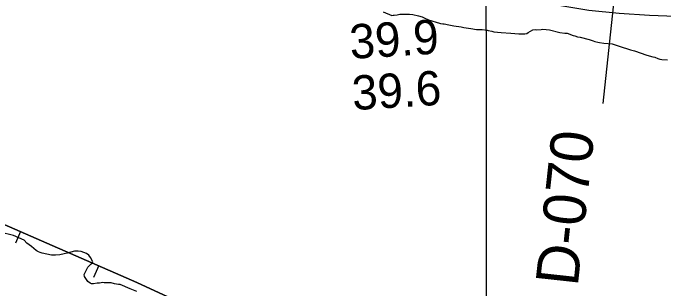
# Model space of a CAD drawing. Extents: x 3279314 to 3317160, y 734079 to 759431.
# Drawn here: x 3290400 to 3291669, y 751596 to 752135 of the extents above; entities that cross this region are included whole.
import ezdxf

# ---------------------------------------------------------------- set-up
doc = ezdxf.new("R2010")
doc.units = 0
for name, color, linetype in [('V-BORW-LINE', 7, 'Continuous'), ('V-GRID-MAJR', 7, 'Continuous'), ('V-RIVR-RANG', 7, 'Continuous'), ('V-RIVR-RANG-IDEN', 7, 'Continuous'), ('V-SITE-VEGE', 7, 'Continuous'), ('V-TOPO-MINR', 7, 'Continuous')]:
    doc.layers.add(name, color=color, linetype=linetype)

msp = doc.modelspace()

# ---------------------------------------------------------------- linework, layer by layer
at = {"layer": 'V-BORW-LINE'}
for p, q in [((3290414.3, 751708.5), (3290404.3, 751685.6)), ((3290567.1, 751642), (3290557.1, 751619))]:
    msp.add_line(p, q, dxfattribs=at)
for points in [[(3287842.3, 752588.2), (3288177.4, 752462.4), (3288402.9, 752400.4), (3288618.4, 752337.5), (3288751.8, 752316.1), (3288970.3, 752257.8), (3289060.5, 752199.2), (3289159, 752171.1), (3289219.5, 752157.3), (3289674.3, 751981.9), (3289836.5, 751953.1), (3290237.3, 751785.6), (3290641.7, 751609.4), (3291148.6, 751375)], [(3291148.6, 751375), (3290641.7, 751609.4), (3290237.3, 751785.6), (3289836.5, 751953.1), (3289674.3, 751981.9), (3289219.5, 752157.3), (3289159, 752171.1), (3289060.5, 752199.2), (3288970.3, 752257.8), (3288751.8, 752316.1), (3288618.4, 752337.5), (3288402.9, 752400.4), (3288177.4, 752462.4), (3287842.3, 752588.2)]]:
    msp.add_lwpolyline(points, dxfattribs=at)
at = {"layer": 'V-GRID-MAJR'}
msp.add_spline([(3291328, 739459.9), (3291326.2, 745519.1), (3291324.4, 751580.9), (3291322.7, 757642.8), (3291322.7, 757645.4)], degree=3, dxfattribs=at)
at = {"layer": 'V-RIVR-RANG'}
msp.add_line((3291552.7, 751958.4), (3291652, 752893.1), dxfattribs=at)
at = {"layer": 'V-SITE-VEGE'}
for points in [[(3291122.5, 752137.5), (3291139.8, 752129.8), (3291142, 752130.4), (3291144.2, 752131), (3291150.3, 752131.6), (3291155.3, 752132.7), (3291174.1, 752132.8), (3291180.8, 752131.7), (3291191.9, 752129.6), (3291199.1, 752127.4), (3291203, 752125.2), (3291211.4, 752121.9), (3291232.5, 752114.8), (3291234.7, 752114.3), (3291239.2, 752113.7), (3291241.9, 752113.7), (3291250.8, 752111.6), (3291260.8, 752110), (3291275.3, 752107.8), (3291280.3, 752106.7), (3291294.2, 752104.6), (3291305.3, 752103), (3291315.8, 752102.5), (3291325.8, 752101.4), (3291328, 752100.9), (3291335.2, 752099.3), (3291338.6, 752098.2), (3291353, 752096.6), (3291371.9, 752095.6), (3291388, 752094.6), (3291394.6, 752094.1), (3291399.1, 752094.1), (3291403, 752095.2), (3291405.7, 752096.9), (3291415.1, 752101.9), (3291420.1, 752102.5), (3291422.9, 752102), (3291431.2, 752102.6), (3291434.5, 752103.2), (3291447.3, 752102.1), (3291467.9, 752097.2), (3291477.3, 752095.6), (3291481.8, 752095.6), (3291494, 752091.3), (3291496.8, 752090.7), (3291502.3, 752088.5), (3291507.3, 752087.5), (3291525.1, 752083.1), (3291532.9, 752080.4), (3291536.2, 752079.3), (3291541.8, 752077.7), (3291545.1, 752077.1), (3291554, 752076.1), (3291570.1, 752074.5), (3291584, 752070.1), (3291605.7, 752063), (3291613.4, 752061.4), (3291637.9, 752052.7), (3291649.6, 752049.4), (3291653.5, 752048.9), (3291659, 752046.1), (3291662.9, 752045), (3291666.8, 752044.5), (3291677.9, 752043.5)], [(3290641.4, 751591.3), (3290628.1, 751596.8), (3290609.2, 751605), (3290605.8, 751605.5), (3290597.5, 751606.6), (3290591.4, 751608.2), (3290588.1, 751608.2), (3290577.5, 751608.7), (3290574.8, 751609.3), (3290568.7, 751608.1), (3290563.7, 751607.5), (3290557, 751606.4), (3290552.6, 751606.4), (3290550.3, 751607.5), (3290545.9, 751611.3), (3290539.2, 751620.7), (3290538.6, 751624.6), (3290545.7, 751639.1), (3290547.4, 751640.7), (3290552.4, 751645.2), (3290554, 751646.9), (3290555.7, 751649.7), (3290551.2, 751658), (3290547.8, 751662.4), (3290542.8, 751665.7), (3290532.8, 751669.5), (3290526.7, 751670), (3290520, 751670), (3290505.6, 751666.6), (3290499.5, 751664.9), (3290490.7, 751663.2), (3290482.4, 751662.6), (3290474.6, 751662.5), (3290456.3, 751666.3), (3290452.4, 751667.4), (3290449.6, 751669.1), (3290446.8, 751670.1), (3290445.1, 751671.8), (3290440.1, 751675.1), (3290435.7, 751679.5), (3290426.7, 751686.1), (3290421.2, 751691.6), (3290400.6, 751701), (3290373.4, 751707.5)]]:
    msp.add_lwpolyline(points, dxfattribs=at)
at = {"layer": 'V-TOPO-MINR'}
msp.add_lwpolyline([(3290142.2, 752521.6), (3291142.8, 752203.9), (3291155.6, 752201.5), (3291168.5, 752199.3), (3291181.5, 752197.4), (3291194.5, 752195.8), (3291207.5, 752194.5), (3291220.5, 752193.2), (3291233.6, 752192), (3291246.6, 752190.9), (3291255.8, 752190.2), (3291273.3, 752188.4), (3291290.8, 752186.1), (3291308.2, 752183.1), (3291325.5, 752179.6), (3291407.4, 752161.4), (3291465.8, 752150), (3291524.4, 752140.7), (3291583.5, 752134.7), (3291642.9, 752130.8), (3291933.2, 752119.7)], dxfattribs=at)

# ---------------------------------------------------------------- texts
at = {"layer": 'V-RIVR-RANG'}
for s, p in [('39.9', (3291059, 752045.2)), ('39.6', (3291063.8, 751945.3))]:
    msp.add_text(s, height=67, rotation=3.5283, dxfattribs=at).set_placement(p)
at = {"layer": 'V-RIVR-RANG-IDEN'}
msp.add_text('D-070', height=83, rotation=83.7923, dxfattribs=at).set_placement((3291502.7, 751600.1))

doc.saveas('drawing.dxf')
